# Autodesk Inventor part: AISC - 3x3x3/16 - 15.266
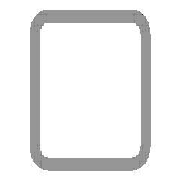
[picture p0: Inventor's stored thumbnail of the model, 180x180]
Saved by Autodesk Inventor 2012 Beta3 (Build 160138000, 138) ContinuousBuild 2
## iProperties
IsCustomPart: 1
Created: 2011-01
Part Number: AISC - 3x3x3/16 - 15.266
Material: Steel, Mild
Description: Tube
Document SubType Name: Modeling
Standard: ANSI
Designer: Beta-8540w
Standards Organization: ANSI
Language: en-US
Size Designation: 3x3x3/16
Categories: <MemberInstance><Categories><Category DisplayName="Structural Shapes" InternalName="089c4875-fa83-4c05-b084-43b9cc11f5ed" Mnemonic="GRDR"><CategoryParameter Dis
Stock Number: 3x3x3/16
Density: 7.86 g/cm^3
_CCFamilyMember: 9
_CCFamilyDisplayName: ANSI AISC (Square) - Tube
_FrameMemberDoc: Frame Member File
_Version: 15.0.0
_GetPNFromCC: 1
G_L: 15.266 in
G_W: 3.000 in
G_H: 3.000 in
+FD2FA98F-6131-4ED7-8715-576CB225FAC2+CUTDETAIL1: Cut
+6EE38D32-1A45-4B16-9B4C-47EFE8477959+CUTDETAIL2: Cut
Author: Beta-8540w
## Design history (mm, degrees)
node "Start plane"
node "End plane"
sketch "Sketch"
  geometry: L1 (-38.1, -28.575)-(-38.1, 28.575); L2 (-28.575, 38.1)-(28.575, 38.1); L3 (38.1, 28.575)-(38.1, -28.575); L4 (28.575, -38.1)-(-28.575, -38.1); L5 (-28.575, 33.337)-(28.575, 33.338); L6 (33.338, 28.575)-(33.338, -28.575); L7 (28.575, -33.337)-(-28.575, -33.338); L8 (-33.338, -28.575)-(-33.338, 28.575); L9 (0, 56.102)-(0, -56.102) reference; L10 (-56.102, 0)-(56.102, 0) reference; A1 r 9.525 centre (-28.575, -28.575) between (-38.1, -28.575) and (-28.575, -38.1); A2 r 9.525 centre (-28.575, 28.575) between (-28.575, 38.1) and (-38.1, 28.575); A3 r 9.525 centre (28.575, 28.575) between (38.1, 28.575) and (28.575, 38.1); A4 r 9.525 centre (28.575, -28.575) between (28.575, -38.1) and (38.1, -28.575); A5 r 4.763 centre (-28.575, 28.575) between (-28.575, 33.337) and (-33.338, 28.575); A6 r 4.763 centre (28.575, 28.575) between (33.338, 28.575) and (28.575, 33.338); A7 r 4.763 centre (28.575, -28.575) between (28.575, -33.337) and (33.338, -28.575); A8 r 4.763 centre (-28.575, -28.575) between (-33.338, -28.575) and (-28.575, -33.338)
  constraints: 16 end point, 16 point on circle, 8 centre point, 8 tangent, 4 parallel, 3 equal radius, 2 perpendicular, 7 other
  dimensions: "d10" = 76.2 distance between parallel lines of L2 L4 (= G_H); "d11" = 76.2 distance between parallel lines of L1 L3 (= G_W); "d12" = 4.7625 distance between parallel lines of L3 L6 (= G_T); "d15" = 38.1 distance between parallel lines of L2 L10 (= 0.5 x d10); "d16" = 38.1 distance between parallel lines of L9 L3 (= 0.5 x d11); "d17" = 9.525 radius of A1 (= G_IR)
extrude "Body" new body sketch "Sketch" stored distance "d3" = 387.75605 (= G_L); taper "d4" = 0 deg
node "Driven Length"
  sketch "Sketch3"
    geometry: L1 (0, 0)-(10, 0) reference
    constraints: 2 end point, 1 horizontal
  workplane "Work Plane3"
  sketch "Sketch4"
    geometry: L1 (-2, 31.109)-(12, 31.109) reference; L2 (-2, 418.865)-(12, 418.865) reference
    dimensions: "d19" = 387.75605 distance between parallel lines of L1 L2 (derived)
workplane "Work Plane4"
split "Split1"
workplane "Work Plane5"
split "Split2"
body "Solid1"
other parameters: "G_W" = 76.2 [user parameter; used in 1 equation term], "G_H" = 76.2 [user parameter; used in 1 equation term], "G_T" = 4.7625 [user parameter; used in 1 equation term], "G_IR" = 9.525 [user parameter; used in 1 equation term], "G_L" = 387.75605 (= d19) [user parameter; used in 1 equation term], "G_OFFSET_START" = -31.10852 [user parameter; used in 1 equation term], "G_OFFSET_END" = -31.10852 [user parameter; used in 1 equation term], "d13" = 31.10852 (= -G_OFFSET_START), "d14" = 418.86457 (= G_OFFSET_END + B_L), "B_L" = 449.97309 [user parameter; used in 1 equation term], "d18" = 90 deg
